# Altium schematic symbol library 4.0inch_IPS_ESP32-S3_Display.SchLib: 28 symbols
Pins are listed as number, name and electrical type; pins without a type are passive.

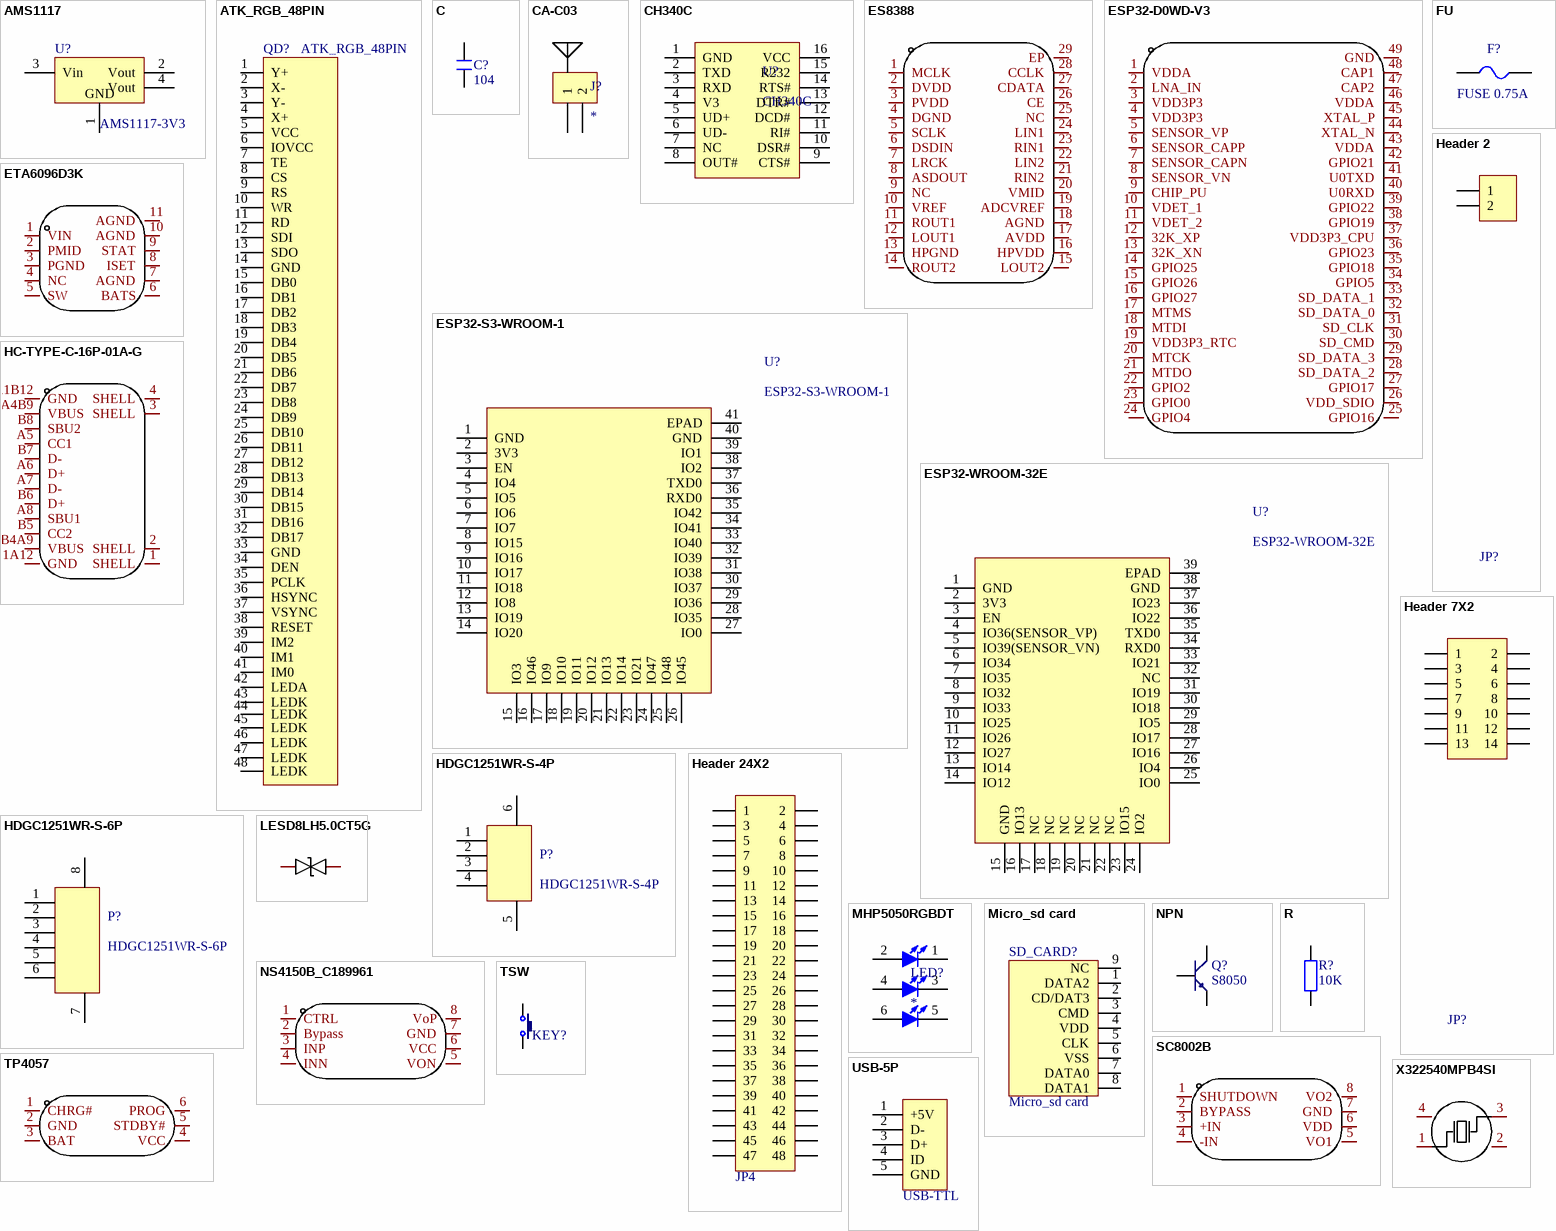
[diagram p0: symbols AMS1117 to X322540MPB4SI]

## AMS1117
designator U?, comment AMS1117-3V3
三端稳压芯片; BOM名称: 稳压芯片; 版权归属: 源创客
footprint SOT89_L (4.6x4.3x1.6mm(长宽高))
pins: 1 GND, 2 Vout, 3 Vin, 4 Vout

## ATK_RGB_48PIN
designator QD?
48pin FPC连接器
footprint 4.3-40P
footprint 5.0INCH-40PIN
footprint FPC-40PIN
footprint FPC-TOP40
pins: 1 Y+, 2 X-, 3 Y-, 4 X+, 5 VCC, 6 IOVCC, 7 TE, 8 CS, 9 RS, 10 WR, 11 RD, 12 SDI, 13 SDO, 14 GND, 15 DB0, 16 DB1, 17 DB2, 18 DB3, 19 DB4, 20 DB5, 21 DB6, 22 DB7, 23 DB8, 24 DB9, 25 DB10, 26 DB11, 27 DB12, 28 DB13, 29 DB14, 30 DB15, 31 DB16, 32 DB17, 33 GND, 34 DEN, 35 PCLK, 36 HSYNC, 37 VSYNC, 38 RESET, 39 IM2, 40 IM1, 41 IM0, 42 LEDA, 43 LEDK, 44 LEDK, 45 LEDK, 46 LEDK, 47 LEDK, 48 LEDK

## C
designator C?, comment 104
无极性贴片电容; 版权归属: 源创客; 材质: X7R
footprint C 0805 (无极性贴片电容)
pins: 1, 2

## CA-C03
designator J?
陶瓷贴片天线
pins: 1, 2

## CH340C
designator U?
USB转串口IC
pins: 1 GND, 2 TXD, 3 RXD, 4 V3, 5 UD+, 6 UD-, 7 NC, 8 OUT#, 9 CTS#, 10 DSR#, 11 RI#, 12 DCD#, 13 DTR#, 14 RTS#, 15 R232, 16 VCC

## ES8388
designator U?  (value not drawn)
Manufacturer: Everest-semi(顺芯); Add into BOM: yes
footprint QFN-28_L4.0-W4.0-P0.45-BL-EP
pins: 1 MCLK, 2 DVDD, 3 PVDD, 4 DGND, 5 SCLK, 6 DSDIN, 7 LRCK, 8 ASDOUT, 9 NC, 10 VREF, 11 ROUT1, 12 LOUT1, 13 HPGND, 14 ROUT2, 15 LOUT2, 16 HPVDD, 17 AVDD, 18 AGND, 19 ADCVREF, 20 VMID, 21 RIN2, 22 LIN2, 23 RIN1, 24 LIN1, 25 NC, 26 CE, 27 CDATA, 28 CCLK, 29 EP

## ESP32-D0WD-V3
designator U?  (value not drawn)
Manufacturer: ESPRESSIF(乐鑫); Add into BOM: yes
footprint QFN-48_L5.0-W5.0-P0.35-BL-EP3.7
pins: 1 VDDA, 2 LNA_IN, 3 VDD3P3, 4 VDD3P3, 5 SENSOR_VP, 6 SENSOR_CAPP, 7 SENSOR_CAPN, 8 SENSOR_VN, 9 CHIP_PU, 10 VDET_1, 11 VDET_2, 12 32K_XP, 13 32K_XN, 14 GPIO25, 15 GPIO26, 16 GPIO27, 17 MTMS, 18 MTDI, 19 VDD3P3_RTC, 20 MTCK, 21 MTDO, 22 GPIO2, 23 GPIO0, 24 GPIO4, 25 GPIO16, 26 VDD_SDIO, 27 GPIO17, 28 SD_DATA_2, 29 SD_DATA_3, 30 SD_CMD, 31 SD_CLK, 32 SD_DATA_0, 33 SD_DATA_1, 34 GPIO5, 35 GPIO18, 36 GPIO23, 37 VDD3P3_CPU, 38 GPIO19, 39 GPIO22, 40 U0RXD, 41 U0TXD, 42 GPIO21, 43 VDDA, 44 XTAL_N, 45 XTAL_P, 46 VDDA, 47 CAP2, 48 CAP1, 49 GND

## ESP32-S3-WROOM-1
designator U?
ESP32-S3-WROOM-1 module
pins: 1 GND, 2 3V3, 3 EN, 4 IO4, 5 IO5, 6 IO6, 7 IO7, 8 IO15, 9 IO16, 10 IO17, 11 IO18, 12 IO8, 13 IO19, 14 IO20, 15 IO3, 16 IO46, 17 IO9, 18 IO10, 19 IO11, 20 IO12, 21 IO13, 22 IO14, 23 IO21, 24 IO47, 25 IO48, 26 IO45, 27 IO0, 28 IO35, 29 IO36, 30 IO37, 31 IO38, 32 IO39, 33 IO40, 34 IO41, 35 IO42, 36 RXD0, 37 TXD0, 38 IO2, 39 IO1, 40 GND, 41 EPAD

## ESP32-WROOM-32E
designator U?
ESP32-WROOM-32E module
pins: 1 GND, 2 3V3, 3 EN, 4 IO36(SENSOR_VP), 5 IO39(SENSOR_VN), 6 IO34, 7 IO35, 8 IO32, 9 IO33, 10 IO25, 11 IO26, 12 IO27, 13 IO14, 14 IO12, 15 GND, 16 IO13, 17 NC, 18 NC, 19 NC, 20 NC, 21 NC, 22 NC, 23 IO15, 24 IO2, 25 IO0, 26 IO4, 27 IO16, 28 IO17, 29 IO5, 30 IO18, 31 IO19, 32 NC, 33 IO21, 34 RXD0, 35 TXD0, 36 IO22, 37 IO23, 38 GND, 39 EPAD

## ETA6096D3K
designator U?  (value not drawn)
Manufacturer: ETA(钰泰）; Add into BOM: yes
footprint DFN-10_L3.0-W3.0-P0.50-BL-EP2.4-1
pins: 1 VIN, 2 PMID, 3 PGND, 4 NC, 5 SW, 6 BATS, 7 AGND, 8 ISET, 9 STAT, 10 AGND, 11 AGND

## FU
designator F?, comment FUSE 0.75A
贴片保险丝; 版权归属: 源创客
footprint FU 0805 (贴片保险丝)
footprint FU 0612 (贴片保险丝)
footprint FU 0805 (贴片保险丝)
pins: 1, 2

## HC-TYPE-C-16P-01A-G
designator USB1  (value not drawn)
Manufacturer: HCTL(华灿天禄); Add into BOM: yes; Connector Type: Type-C; Gender: 母座; Number of Contacts: 16; Number of Ports: 1
3D model USB-C-SMD_G-SWITCH_GT-USB-7010EN
footprint USB-C-SMD_G-SWITCH_GT-USB-7010EN
footprint USB-C-SMD_G-SWITCH_GT-USB-7010EN
pins: 1 SHELL, 2 SHELL, 3 SHELL, 4 SHELL, A1B12 GND, A4B9 VBUS, A5 CC1, A6 D+, A7 D-, A8 SBU1, B1A12 GND, B4A9 VBUS, B5 CC2, B6 D+, B7 D-, B8 SBU2

## HDGC1251WR-S-4P
designator P?
pins: 1, 2, 3, 4, 5, 6

## HDGC1251WR-S-6P
designator P?
pins: 1, 2, 3, 4, 5, 6, 7, 8

## Header 2
designator JP?  (value not drawn)
2P接插件; BOM名称: 20*2P接插件; 版权归属: 源创客
footprint HDR2.54-LI-2X24P (双排排针，24x2脚)
pins: 1, 2

## Header 7X2
designator JP?, comment Header 2X7  (value not drawn)
7*2P接插件; BOM名称: 20*2P接插件; 版权归属: 源创客
footprint HDR2.54-LI-2X24P (双排排针，24x2脚)
pins: 1, 2, 3, 4, 5, 6, 7, 8, 9, 10, 11, 12, 13, 14

## Header 24X2
designator JP4, comment Header 2X24  (value not drawn)
24*2P接插件; BOM名称: 20*2P接插件; 版权归属: 源创客
footprint HDR2.54-LI-2X24P (双排排针，24x2脚)
pins: 1, 2, 3, 4, 5, 6, 7, 8, 9, 10, 11, 12, 13, 14, 15, 16, 17, 18, 19, 20, 21, 22, 23, 24, 25, 26, 27, 28, 29, 30, 31, 32, 33, 34, 35, 36, 37, 38, 39, 40, 41, 42, 43, 44, 45, 46, 47, 48

## LESD8LH5.0CT5G
designator D?  (value not drawn)
Manufacturer: LRC(乐山无线电); Add into BOM: yes; Reverse Stand-Off Voltage (Vrwm): 5V; Maximum Clamping Voltage: 11.5V; Peak Pulse Current (Ipp)@10/1000us: 3.5A@8/20us; Breakdown Voltage: 5.5V; Type: TVS
footprint SOD-882_L1.0-W0.6-BI
pins: 1, 2

## MHP5050RGBDT
designator LED?
RGB LED
pins: 1 K, 2 A, 3 K, 4 A, 5 K, 6 A

## Micro_sd card
designator SD_CARD?
miniSD卡卡槽
footprint MicroTF
pins: 1 DATA2, 2 CD/DAT3, 3 CMD, 4 VDD, 5 CLK, 6 VSS, 7 DATA0, 8 DATA1, 9 NC

## NPN
designator Q?, comment S8050
8050/BCW846/BCW847
footprint SOT-23R
footprint NPN
pins: 1 E, 2 B, 3 C

## NS4150B_C189961
designator U?  (value not drawn)
Manufacturer: Nsiway(纳芯威); Symbol: NS4150; Add into BOM: yes; Type of Power Amplifier: D类功放; Output Power: 3Wx1@4Ω; Supply Voltage: 3V~5.25V
footprint MSOP-8_L3.0-W3.0-P0.65-LS5.0-BL
pins: 1 CTRL, 2 Bypass, 3 INP, 4 INN, 5 VON, 6 VCC, 7 GND, 8 VoP

## R
designator R?, comment 10K
贴片电阻; 版权归属: 源创客
footprint R0603
pins: 1, 2

## SC8002B
designator U?  (value not drawn)
Manufacturer: FM(富满); Add into BOM: yes; Speaker Channels: 单声道; Output Power: 2.5Wx1@4Ω; Supply Voltage: 2V~5V
footprint SOP-8_L4.9-W3.9-P1.27-LS6.0-BL
pins: 1 SHUTDOWN, 2 BYPASS, 3 +IN, 4 -IN, 5 VO1, 6 VDD, 7 GND, 8 VO2

## TP4057
designator U?  (value not drawn)
Manufacturer: UMW(友台半导体); Symbol: TP4057_C725791; Add into BOM: yes; Supply Voltage: 6.5V; Maximum Charge Current: 500mA; Type of Battery: 锂离子/聚合物; Number of Cells: 1
footprint SOT-23-6_L2.9-W1.6-P0.95-LS2.8-BR
pins: 1 CHRG#, 2 GND, 3 BAT, 4 VCC, 5 STDBY#, 6 PROG

## TSW
designator KEY?, comment 3x6x5  (value not drawn)
轻触开关; BOM名称: 3x6轻触开关; 版权归属: 源创客
footprint TSW SMD-3*4*2.5 (3*4*2.5mm)
pins: 1, 2

## USB-5P
designator USB?, comment USB-TTL
微型USB母座; 版权归属: 源创客
footprint Micro_USB2 (Micro_USB Dock 5 Pin)
pins: 1 +5V, 2 D-, 3 D+, 4 ID, 5 GND

## X322540MPB4SI
designator X?  (value not drawn)
Manufacturer: YXC(扬兴晶振); Value: 40MHz; Add into BOM: yes; Crystal Type: 贴片晶振; Normal temperature Frequency Tolerance: ±10ppm; External load capacitor: 15pF; Frequency Stability(Full temperature range): ±30ppm
footprint OSC-SMD_4P-L3.2-W2.5-BL_SIT8008BI
pins: 1 OSC1, 2 GND, 3 OSC2, 4 GND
